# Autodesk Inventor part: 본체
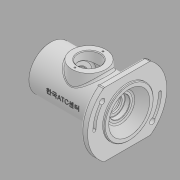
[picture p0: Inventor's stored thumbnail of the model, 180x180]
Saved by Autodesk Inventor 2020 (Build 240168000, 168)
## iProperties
Created: 2022-05
Part Number: 본체
Material: 일반
Document SubType Name: Modeling
Designer: User
Density: 1 g/cm^3
Appearance: 기본값
Mass: 254.372 g
Surface Area: 618.889 cm^2
Volume: 254.372 cm^3
Author: User
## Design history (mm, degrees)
sketch "스케치1"
  geometry: L1 (0, 0)-(0, 32); L2 (115, 0)-(0, 0); L3 (8, 22.5)-(8, 24); L4 (8, 24)-(11, 24); L5 (11, 24)-(11, 22.5); L6 (11, 22.5)-(22, 22.5); L7 (22, 22.5)-(22, 17.5); L8 (22, 17.5)-(24.25, 17.5); L9 (24.25, 17.5)-(24.25, 18.5); L10 (24.25, 18.5)-(26, 18.5); L11 (26, 18.5)-(26, 17.5); L12 (26, 17.5)-(37, 17.5); L13 (37, 17.5)-(37, 27); L14 (37, 27)-(75, 27); L15 (75, 27)-(75, 17.5); L16 (75, 17.5)-(86, 17.5); L17 (86, 17.5)-(86, 15); L18 (86, 15)-(91, 15); L19 (91, 15)-(91, 11); L20 (91, 11)-(93.7, 11); L21 (0, 32)-(102, 32); L22 (102, 32)-(102, 36); L23 (102, 36)-(115, 36); L24 (115, 36)-(115, 0); L25 (101, 20)-(115, 30); L26 (8, 22.5)-(0, 22.5); L27 (101, 20)-(101, 15); L28 (101, 15)-(93.7, 15); L29 (93.7, 15)-(93.7, 11); L30 (97.35, 15)-(97.35, 0)
  constraints: 60 end point, 22 perpendicular, 5 point on line, 3 vertical, 1 horizontal, 1 midpoint
  dimensions: "d1" = 115 distance of L2.start L1.start; "d3" = 13 distance of L22.end L23.end; "d4" = 72 diameter of L23 L2; "d5" = 64 diameter of L21 L2; "d6" = 60 diameter of L25.end L2; "d7" = 40 diameter of L25.start L2; "d8" = 14 horizontal distance of L25.end L25.start; "d10" = 45 diameter of L26 L2; "d11" = 48 diameter of L4 L2; "d12" = 45 diameter of L6 L2; "d13" = 35 diameter of L8 L2; "d14" = 37 diameter of L10 L2; "d15" = 35 diameter of L12 L2; "d16" = 54 diameter of L14 L2; "d17" = 30 diameter of L18 L2; "d18" = 22 diameter of L20 L2; "d19" = 30 diameter of L28 L2; "d20" = 5 distance of L17.end L18.end; "d21" = 11 distance of L15.end L16.end; "d22" = 38 distance of L13.end L14.end; "d23" = 11 distance of L11.end L12.end; "d24" = 8 distance of L3.start L26.end; "d25" = 3 distance of L3.end L4.end; "d26" = 22 distance from line of L6.end L1; "d27" = 4 distance between parallel lines of L11 L7; "d28" = 1.75 distance of L9.end L10.end; "d29" = 2.7 distance of L19.end L20.end
revolve "회전1" stored, may be unused: angle "d30" = 90 deg
node "작업 평면1"
sketch "스케치2"
  geometry: L1 (0, 0)-(0, 58); L2 (-47, 0)-(-47, 33.985); L3 (0, 0)-(-47, 0); L4 (47, 0)-(47, 33.985); L5 (47, 0)-(47, -33.985); L6 (-47, 0)-(-47, -33.985); A1 r 58 centre (0, 0) between (-47, -33.985) and (47, -33.985); A2 r 58 centre (0, 0) between (47, 33.985) and (-47, 33.985); 1 further point
  constraints: 12 end point, 5 point on circle, 4 symmetric about line, 2 centre point, 1 coincident, 1 parallel, 1 perpendicular, 1 vertical
  dimensions: "d33" = 47 distance between parallel lines of L1 L2; "d34" = 58 radius of A2
extrude "돌출1" join sketch "스케치2" distance "d35" = 10; taper "d36" = 0 deg
revolve "회전2" stored, may be unused: angle "d37" = 90 deg
sketch "스케치3"
  geometry: L1 (0, 0)-(-48, 0); L2 (0, 0)-(-48.362, -48.362); A1 r 48 centre (0, 0) between (-48, 0) and (-33.941, -33.941); A2 r 48 centre (0, 0) between (-48, 0) and (-33.941, -33.941); 1 further point
  constraints: 4 end point, 4 point on circle, 2 centre point, 1 coincident, 1 concentric, 1 horizontal, 1 point on line
  dimensions: "d38" = 96 diameter of A1; "d39" = 45 deg angle of L2 L1
node "작업 평면2"
sketch "스케치4"
  geometry: L1 (0, 32)-(0, -32) reference; C1 r 25 at (-56, 0); 2 further points
  constraints: 1 centre point, 1 horizontal alignment, 1 midpoint
  dimensions: "d42" = 50 diameter of C1; "d43" = 56 distance from line of C1.centre L1
extrude "돌출2" join sketch "스케치4" stored distance "d44" = 13; taper "d45" = 5 deg
sketch "스케치5"
  geometry: C1 r 25 at (0, 0) reference; C2 r 16 at (0, 0); 1 further point
  constraints: 1 centre point, 1 coincident
  dimensions: "d46" = 32 diameter of C2
extrude "돌출3" cut sketch "스케치5" stored distance "d47" = 13; taper "d48" = 0 deg
sketch "스케치6"
  geometry: L1 (-33.985, -47)-(33.985, -47) reference; L2 (33.985, 47)-(-33.985, 47) reference; L3 (0, 0)-(-48, 0); L4 (0, 0)-(-36.77, -30.854); L5 (0, 0)-(36.77, 30.854); L6 (0, 0)-(48, 0); C1 r 36 at (0, 0) reference; A1 r 58 centre (0, 0) between (33.985, -47) and (33.985, 47) reference; A2 r 58 centre (0, 0) between (-33.985, 47) and (-33.985, -47) reference; A3 r 48 centre (0, 0) between (-48, 0) and (-36.77, -30.854); 3 further points
  constraints: 8 end point, 4 point on circle, 3 coincident, 2 horizontal, 1 centre point
  dimensions: "d49" = 96 diameter of A3; "d50" = 40 deg angle of L4 L3; "d51" = 40 deg angle of L6 L5
hole "구멍1" sketch "스케치6" at (-36.77, -30.854), (36.77, 30.854) diameter "d52" = 8; stored, may be unused: countersink angle "d56" = 90 deg, drill point angle "d58" = 118 deg; dims "d53" = 8, "d54" = 8, "d55" = 4.4, "d57" = 10
sketch "스케치7"
  geometry: L1 (33.985, -47)-(-33.985, -47) reference; L2 (-33.985, 47)-(33.985, 47) reference; L3 (0, 0)-(-48, 0); L4 (0, 0)-(48, 0); C1 r 4 at (36.77, -30.854) reference; C2 r 4 at (-36.77, 30.854) reference; C3 r 36 at (0, 0) reference; A1 r 58 centre (0, 0) between (-33.985, 47) and (-33.985, -47) reference; A2 r 58 centre (0, 0) between (33.985, -47) and (33.985, 47) reference; A3 r 48 centre (0, 0) between (-48, 0) and (48, 0); A4 r 48 centre (0, 0) between (-36.77, 30.854) and (-48, 0); A5 r 50.25 centre (0, 0) between (-38.494, 32.3) and (-50.25, 0); A6 r 45.75 centre (0, 0) between (-35.047, 29.408) and (-45.75, 0); A7 r 2.25 centre (-36.77, 30.854) between (-35.047, 29.408) and (-38.494, 32.3); A8 r 2.25 centre (-48, 0) between (-50.25, 0) and (-45.75, 0); A9 r 48 centre (0, 0) between (36.77, -30.854) and (48, 0); A10 r 48 centre (0, 0) between (36.77, -30.854) and (48, 0); A11 r 50.25 centre (0, 0) between (38.494, -32.3) and (50.25, 0); A12 r 45.75 centre (0, 0) between (35.047, -29.408) and (45.75, 0); A13 r 2.25 centre (36.77, -30.854) between (35.047, -29.408) and (38.494, -32.3); A14 r 2.25 centre (48, 0) between (50.25, 0) and (45.75, 0); 3 further points
  constraints: 24 point on circle, 12 centre point, 9 tangent, 4 end point, 3 concentric, 2 horizontal, 1 coincident
  dimensions: "d59" = 96 diameter of A3; "d60" = 2.25 radius of A8; "d63" = 2.25 radius of A14
  node "투영된 루프3"
extrude "돌출4" cut sketch "스케치7" extent not by distance; stored distance "d61" = 0; taper "d62" = 0 deg
extrude "돌출5" cut sketch "스케치7" extent not by distance; stored distance "d64" = 10; taper "d65" = 0 deg
sketch "스케치8"
  geometry: L1 (0, 0)-(0, 20.5); L2 (0, 0)-(0, -20.5); C1 r 16 at (0, 0) reference; C2 r 25 at (0, 0) reference; A1 r 20.5 centre (0, 0) between (0, 20.5) and (0, -20.5); 3 further points
  constraints: 4 end point, 3 coincident, 2 point on circle, 1 centre point, 1 point on line, 1 vertical
  dimensions: "d66" = 41 diameter of A1
hole "구멍2" sketch "스케치8" at (0, 20.5), (0, -20.5) diameter "d67" = 2.459; stored, may be unused: countersink angle "d71" = 82 deg, drill point angle "d73" = 118 deg; dims "d68" = 6, "d69" = 3.023, "d70" = 4400, "d72" = 8
feature "스레드1" dims "d74" = 8, "d75" = 0
fillet "모깎기1" dims "d76" = 3
chamfer "모따기1" distance "d77" = 1; stored, may be unused: second distance "d78" = 2, angle "d79" = 45 deg
chamfer "모따기2" distance "d80" = 1; stored, may be unused: second distance "d81" = 2, angle "d82" = 45 deg
fillet "모깎기2" dims "d83" = 3
fillet "모깎기3" dims "d84" = 0.6
fillet "모깎기4" dims "d85" = 0.5
fillet "모깎기6" dims "d90" = 3
fillet "모깎기7" dims "d91" = 3
fillet "모깎기8" dims "d92" = 3
chamfer "모따기4" distance "d93" = 1; stored, may be unused: second distance "d94" = 2, angle "d95" = 45 deg
node "작업 평면3"
sketch "스케치9"
  geometry: L1 (26.906, 4.949)-(73.094, 4.949); L2 (73.094, 4.949)-(73.094, -4.949); L3 (73.094, -4.949)-(26.906, -4.949); L4 (26.906, -4.949)-(26.906, 4.949); L5 (26.906, 4.949)-(73.094, -4.949); L6 (73.094, 4.949)-(26.906, -4.949); L7 (112, 46.4)-(112, -46.4) reference; 3 further points
  constraints: 4 end point, 2 midpoint, 1 horizontal alignment, 2 other
  dimensions: "d97" = 62 distance from line of point (50, 0) L7
feature "엠보싱1" sketch "스케치9" dims "d1" = 115, "d8" = 14, "d98" = 0.5, "d99" = 0
sketch "스케치10"
  geometry: L1 (-33, 44)-(33, 44) reference; L2 (33, -44)-(-33, -44) reference; C1 r 35 at (0, 0) reference; C2 r 48 at (0, 0); A1 r 55 centre (0, 0) between (-33, 44) and (-33, -44) reference; A2 r 55 centre (0, 0) between (33, -44) and (33, 44) reference; A3 r 45.75 centre (0, 0) between (45.75, 0) and (37.033, 26.862) reference; A4 r 4 centre (36.77, 30.854) between (40.58, 29.636) and (37.033, 26.862) reference; A5 r 50.25 centre (0, 0) between (50.25, 0) and (40.58, 29.636) reference; A6 r 2.25 centre (48, 0) between (45.75, 0) and (50.25, 0) reference; A7 r 45.75 centre (0, 0) between (-45.75, 0) and (-37.033, -26.862) reference; A8 r 4 centre (-36.77, -30.854) between (-40.58, -29.636) and (-37.033, -26.862) reference; A9 r 50.25 centre (0, 0) between (-50.25, 0) and (-40.58, -29.636) reference; A10 r 2.25 centre (-48, 0) between (-45.75, 0) and (-50.25, 0) reference; A11 r 48 centre (0, 0) between (-48, 0) and (-36.77, -30.854); A12 r 52 centre (0, 0) between (-52, 0) and (-39.834, -33.425); A13 r 44 centre (0, 0) between (-44, 0) and (-33.706, -28.283); A14 r 4 centre (-48, 0) between (-44, 0) and (-52, 0); A15 r 4 centre (-36.77, -30.854) between (-39.834, -33.425) and (-33.706, -28.283); A16 r 48 centre (0, 0) between (48, 0) and (36.77, 30.854); A17 r 52 centre (0, 0) between (52, 0) and (39.834, 33.425); A18 r 44 centre (0, 0) between (44, 0) and (33.706, 28.283); A19 r 4 centre (48, 0) between (44, 0) and (52, 0); A20 r 4 centre (36.77, 30.854) between (39.834, 33.425) and (33.706, 28.283); 5 further points
  constraints: 20 point on circle, 11 centre point, 8 tangent, 4 concentric, 1 coincident
  dimensions: "d100" = 96 diameter of C2
extrude "돌출6" cut sketch "스케치10" distance "d101" = 4.4; taper "d102" = 0 deg
fillet "모깎기9" dims "d103" = 3
chamfer "모따기5" distance "d104" = 0.7; stored, may be unused: second distance "d105" = 2, angle "d106" = 30 deg
node "솔리드1"
node "투영된 루프1"
node "투영된 루프2"
node "투영된 루프4"
node "투영된 루프5"
feature "A9D066F2-1C7D-4E18-AEED-F7BC21143FA4" dims "d74" = 8, "d75" = 0
other parameters: "d31" = -3, "d32" = 116, "d41" = 38, "d96" = 32
